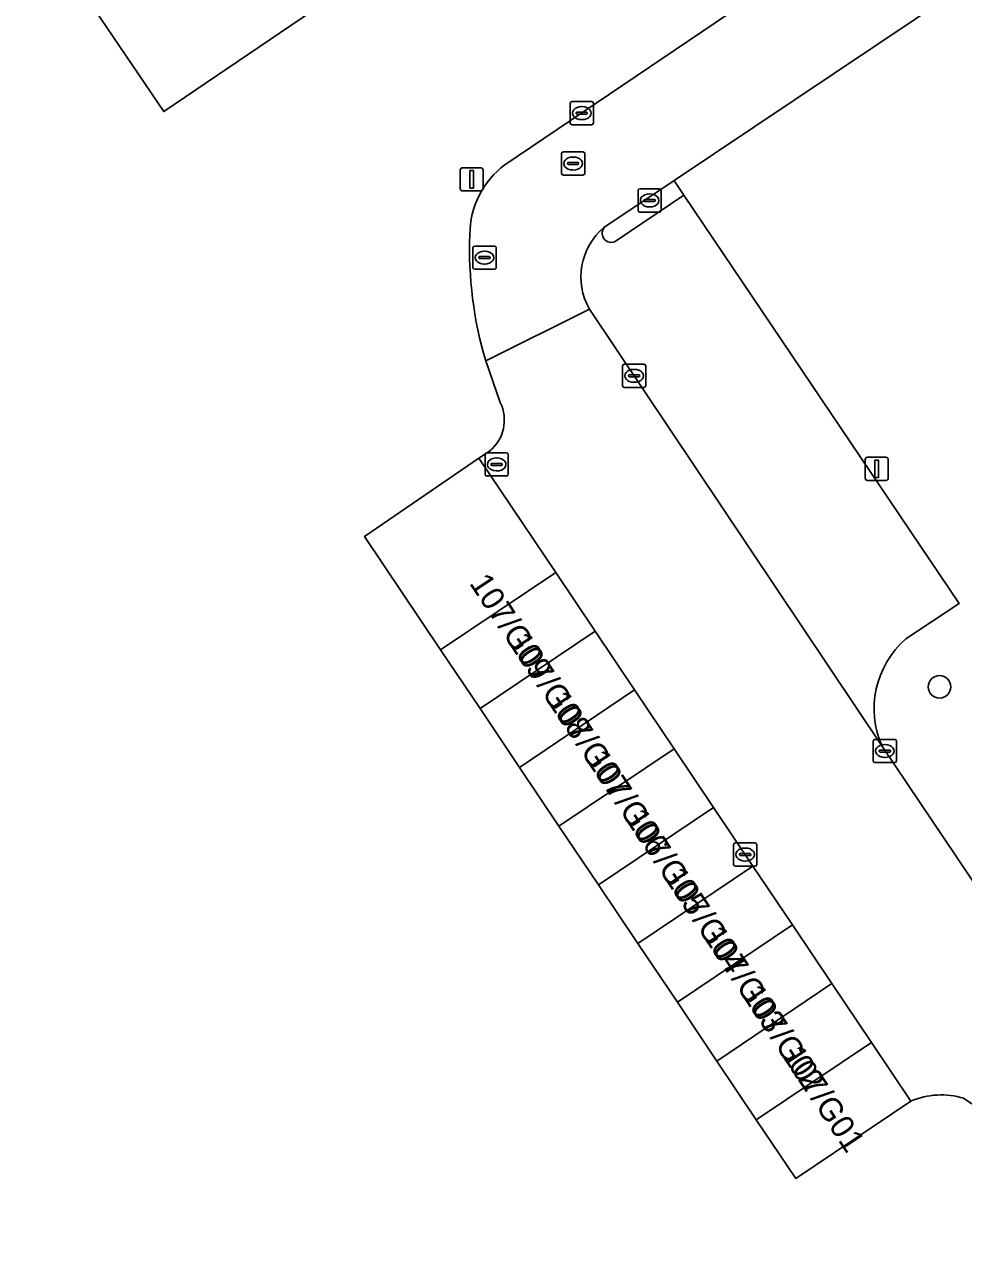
# Model space of a CAD drawing. Extents: x 157445 to 158888, y 383061 to 384688.
# Drawn here: x 157824.2 to 157864.7, y 383505.8 to 383558.3 of the extents above; entities that cross this region are included whole.
import ezdxf

# ---------------------------------------------------------------- set-up
doc = ezdxf.new("R2010")
doc.units = 0
for name, color, linetype in [('IMGEO_Boom', 7, 'Continuous'), ('IMGEO_Brandkraan', 7, 'Continuous'), ('IMGEO_Erf', 7, 'Continuous'), ('IMGEO_Kolk', 7, 'Continuous'), ('IMGEO_Lichtmast', 7, 'Continuous'), ('IMGEO_Pand', 7, 'Continuous'), ('IMGEO_Pand_nummerreeks', 7, 'Continuous'), ('IMGEO_Parkeervlak_open', 7, 'Continuous'), ('IMGEO_Rijbaan_lokaal_open', 7, 'Continuous'), ('IMGEO_Rioolput', 7, 'Continuous'), ('IMGEO_Voetpad_open', 7, 'Continuous')]:
    doc.layers.add(name, color=color, linetype=linetype)

msp = doc.modelspace()

# ---------------------------------------------------------------- linework, layer by layer
at = {"layer": 'IMGEO_Boom'}
msp.add_circle((157863.674, 383529.745), 0.489, dxfattribs=at)
at = {"layer": 'IMGEO_Brandkraan'}
for p, q in [((157847.376, 383551.876), (157847.376, 383552.728)), ((157847.451, 383552.802), (157848.303, 383552.802)), ((157848.377, 383552.728), (157848.377, 383551.876)), ((157847.635, 383552.296), (157847.635, 383552.308)), ((157848.073, 383552.259), (157847.675, 383552.259)), ((157847.678, 383552.345), (157848.076, 383552.345)), ((157847.864, 383552.582), (157847.889, 383552.582)), ((157848.119, 383552.308), (157848.119, 383552.296)), ((157848.303, 383551.802), (157847.451, 383551.802)), ((157847.887, 383552.022), (157847.862, 383552.022))]:
    msp.add_line(p, q, dxfattribs=at)
for points in [[(157847.376, 383551.876), (157847.376, 383552.728)], [(157847.451, 383552.802), (157848.303, 383552.802)], [(157848.377, 383552.728), (157848.377, 383551.876)], [(157848.303, 383551.802), (157847.451, 383551.802)]]:
    msp.add_lwpolyline(points, dxfattribs=at)
for centre, radius, start, end in [((157847.453, 383552.726), 0.0765, 91.552, 178.448), ((157847.453, 383552.726), 0.0765, 91.552, 178.448), ((157848.301, 383552.726), 0.0765, 1.552, 88.448), ((157848.301, 383552.726), 0.0765, 1.552, 88.448), ((157847.675, 383552.305), 0.0403, 85.8775, 175.7526), ((157847.672, 383552.295), 0.0366, 178.938, 274.7102), ((157848.076, 383552.302), 0.043, 264.8664, 352.4533), ((157848.08, 383552.307), 0.0386, 1.7309, 96.639), ((157847.453, 383551.878), 0.0765, 181.552, 268.448), ((157847.453, 383551.878), 0.0765, 181.552, 268.448), ((157848.301, 383551.878), 0.0765, 271.552, 358.448), ((157848.301, 383551.878), 0.0765, 271.552, 358.448)]:
    msp.add_arc(centre, radius, start, end, dxfattribs=at)
for centre, major_axis, ratio, start_param, end_param in [((157847.863, 383552.302), (-0.387, 0.002), 0.722429, 4.712389, 7.853982), ((157847.888, 383552.302), (-0.39, 0.002), 0.717154, 1.570796, 4.712389)]:
    msp.add_ellipse(centre, major_axis=major_axis, ratio=ratio, start_param=start_param, end_param=end_param, dxfattribs=at)
at = {"layer": 'IMGEO_Erf'}
msp.add_lwpolyline([(157844.882, 383564.471), (157830.231, 383554.54), (157824.218, 383563.411), (157838.87, 383573.342), (157853.625, 383583.343), (157868.277, 383593.274), (157874.289, 383584.403), (157859.638, 383574.472)], close=True, dxfattribs=at)
for points in [[(157844.94, 383552.247), (157889.043, 383582.032), (157889.621, 383582.56), (157887.417, 383584.862), (157886.541, 383585.652), (157884.838, 383587.206), (157882.528, 383589.266)], [(157905.879, 383567.073), (157893.465, 383579.161), (157891.88, 383578.119), (157852.229, 383551.572), (157852.305, 383551.459), (157852.656, 383550.938), (157864.518, 383533.336), (157862.221, 383531.81)], [(157844.739, 383541.998), (157844.108, 383543.792)], [(157862.438, 383511.892), (157857.477, 383508.557), (157855.776, 383511.088), (157854.074, 383513.62), (157852.373, 383516.151), (157850.672, 383518.683), (157848.97, 383521.214), (157847.269, 383523.746), (157845.568, 383526.277), (157843.866, 383528.809), (157842.165, 383531.34), (157838.89, 383536.227), (157843.816, 383539.6), (157844.269, 383539.91)], [(157861.211, 383527.166), (157873.422, 383509.028)], [(157869.642, 383505.834), (157866.134, 383511.051), (157864.716, 383512.012)]]:
    msp.add_lwpolyline(points, dxfattribs=at)
for centre, radius, start, end in [((157847.183, 383549.232), 3.758, 126.642, 179.8012), ((157860.364, 383548.597), 16.951, 177.8104, 196.4681), ((157843.203, 383541.247), 1.71, 308.5698, 26.059), ((157864.833, 383528.81), 3.977, 131.0422, 204.418), ((157863.743, 383508.809), 3.348, 73.0947, 112.9362)]:
    msp.add_arc(centre, radius, start, end, dxfattribs=at)
at = {"layer": 'IMGEO_Kolk'}
for p, q in [((157847.752, 383554.047), (157847.752, 383554.899)), ((157847.827, 383554.973), (157848.679, 383554.973)), ((157848.753, 383554.899), (157848.753, 383554.047)), ((157848.011, 383554.467), (157848.011, 383554.479)), ((157848.449, 383554.43), (157848.051, 383554.43)), ((157848.054, 383554.516), (157848.452, 383554.516)), ((157848.24, 383554.753), (157848.265, 383554.753)), ((157848.495, 383554.479), (157848.495, 383554.467)), ((157848.679, 383553.973), (157847.827, 383553.973)), ((157848.263, 383554.193), (157848.238, 383554.193)), ((157850.677, 383550.285), (157850.677, 383551.137)), ((157850.752, 383551.211), (157851.604, 383551.211)), ((157851.678, 383551.137), (157851.678, 383550.285)), ((157850.936, 383550.705), (157850.936, 383550.717)), ((157851.374, 383550.668), (157850.976, 383550.668)), ((157850.979, 383550.754), (157851.377, 383550.754)), ((157851.165, 383550.991), (157851.19, 383550.991)), ((157851.42, 383550.717), (157851.42, 383550.705)), ((157851.604, 383550.211), (157850.752, 383550.211)), ((157851.188, 383550.431), (157851.163, 383550.431)), ((157850.007, 383542.725), (157850.007, 383543.577)), ((157850.082, 383543.651), (157850.934, 383543.651)), ((157850.495, 383543.431), (157850.52, 383543.431)), ((157851.008, 383543.577), (157851.008, 383542.725)), ((157850.266, 383543.145), (157850.266, 383543.157)), ((157850.704, 383543.108), (157850.306, 383543.108)), ((157850.309, 383543.194), (157850.707, 383543.194)), ((157850.518, 383542.871), (157850.493, 383542.871)), ((157850.75, 383543.157), (157850.75, 383543.145)), ((157850.934, 383542.651), (157850.082, 383542.651)), ((157844.081, 383538.908), (157844.081, 383539.76)), ((157844.156, 383539.834), (157845.008, 383539.834)), ((157844.569, 383539.614), (157844.594, 383539.614)), ((157845.082, 383539.76), (157845.082, 383538.908)), ((157844.34, 383539.328), (157844.34, 383539.34)), ((157844.778, 383539.291), (157844.38, 383539.291)), ((157844.383, 383539.377), (157844.781, 383539.377)), ((157844.592, 383539.054), (157844.567, 383539.054)), ((157844.824, 383539.34), (157844.824, 383539.328)), ((157845.008, 383538.834), (157844.156, 383538.834)), ((157860.818, 383526.554), (157860.818, 383527.406)), ((157860.893, 383527.48), (157861.745, 383527.48)), ((157861.077, 383526.974), (157861.077, 383526.986)), ((157861.12, 383527.023), (157861.518, 383527.023)), ((157861.306, 383527.26), (157861.331, 383527.26)), ((157861.561, 383526.986), (157861.561, 383526.974)), ((157861.819, 383527.406), (157861.819, 383526.554)), ((157861.745, 383526.48), (157860.893, 383526.48)), ((157861.515, 383526.937), (157861.117, 383526.937)), ((157861.329, 383526.7), (157861.304, 383526.7)), ((157854.798, 383522.091), (157854.798, 383522.943)), ((157854.873, 383523.017), (157855.725, 383523.017)), ((157855.286, 383522.797), (157855.311, 383522.797)), ((157855.799, 383522.943), (157855.799, 383522.091)), ((157855.057, 383522.511), (157855.057, 383522.523)), ((157855.495, 383522.474), (157855.097, 383522.474)), ((157855.1, 383522.56), (157855.498, 383522.56)), ((157855.541, 383522.523), (157855.541, 383522.511)), ((157855.725, 383522.017), (157854.873, 383522.017)), ((157855.309, 383522.237), (157855.284, 383522.237))]:
    msp.add_line(p, q, dxfattribs=at)
for points in [[(157847.752, 383554.047), (157847.752, 383554.899)], [(157847.827, 383554.973), (157848.679, 383554.973)], [(157848.753, 383554.899), (157848.753, 383554.047)], [(157848.679, 383553.973), (157847.827, 383553.973)], [(157850.677, 383550.285), (157850.677, 383551.137)], [(157850.752, 383551.211), (157851.604, 383551.211)], [(157851.678, 383551.137), (157851.678, 383550.285)], [(157851.604, 383550.211), (157850.752, 383550.211)], [(157850.007, 383542.725), (157850.007, 383543.577)], [(157850.082, 383543.651), (157850.934, 383543.651)], [(157851.008, 383543.577), (157851.008, 383542.725)], [(157850.934, 383542.651), (157850.082, 383542.651)], [(157844.081, 383538.908), (157844.081, 383539.76)], [(157844.156, 383539.834), (157845.008, 383539.834)], [(157845.082, 383539.76), (157845.082, 383538.908)], [(157845.008, 383538.834), (157844.156, 383538.834)], [(157860.818, 383526.554), (157860.818, 383527.406)], [(157860.893, 383527.48), (157861.745, 383527.48)], [(157861.819, 383527.406), (157861.819, 383526.554)], [(157861.745, 383526.48), (157860.893, 383526.48)], [(157854.798, 383522.091), (157854.798, 383522.943)], [(157854.873, 383523.017), (157855.725, 383523.017)], [(157855.799, 383522.943), (157855.799, 383522.091)], [(157855.725, 383522.017), (157854.873, 383522.017)]]:
    msp.add_lwpolyline(points, dxfattribs=at)
for centre, radius, start, end in [((157847.829, 383554.897), 0.0765, 91.552, 178.448), ((157847.829, 383554.897), 0.0765, 91.552, 178.448), ((157848.677, 383554.897), 0.0765, 1.552, 88.448), ((157848.677, 383554.897), 0.0765, 1.552, 88.448), ((157848.051, 383554.476), 0.0403, 85.8775, 175.7526), ((157848.048, 383554.466), 0.0366, 178.938, 274.7102), ((157848.452, 383554.473), 0.043, 264.8664, 352.4533), ((157848.456, 383554.478), 0.0386, 1.7309, 96.639), ((157847.829, 383554.049), 0.0765, 181.552, 268.448), ((157847.829, 383554.049), 0.0765, 181.552, 268.448), ((157848.677, 383554.049), 0.0765, 271.552, 358.448), ((157848.677, 383554.049), 0.0765, 271.552, 358.448), ((157850.754, 383551.135), 0.0765, 91.552, 178.448), ((157850.754, 383551.135), 0.0765, 91.552, 178.448), ((157851.602, 383551.135), 0.0765, 1.552, 88.448), ((157851.602, 383551.135), 0.0765, 1.552, 88.448), ((157850.976, 383550.714), 0.0403, 85.8775, 175.7526), ((157850.973, 383550.704), 0.0366, 178.938, 274.7102), ((157851.377, 383550.711), 0.043, 264.8664, 352.4533), ((157851.381, 383550.716), 0.0386, 1.7309, 96.639), ((157850.754, 383550.287), 0.0765, 181.552, 268.448), ((157850.754, 383550.287), 0.0765, 181.552, 268.448), ((157851.602, 383550.287), 0.0765, 271.552, 358.448), ((157851.602, 383550.287), 0.0765, 271.552, 358.448), ((157850.084, 383543.575), 0.0765, 91.552, 178.448), ((157850.084, 383543.575), 0.0765, 91.552, 178.448), ((157850.932, 383543.575), 0.0765, 1.552, 88.448), ((157850.932, 383543.575), 0.0765, 1.552, 88.448), ((157850.084, 383542.727), 0.0765, 181.552, 268.448), ((157850.084, 383542.727), 0.0765, 181.552, 268.448), ((157850.306, 383543.154), 0.0403, 85.8775, 175.7526), ((157850.303, 383543.144), 0.0366, 178.938, 274.7102), ((157850.707, 383543.151), 0.043, 264.8664, 352.4533), ((157850.711, 383543.156), 0.0386, 1.7309, 96.639), ((157850.932, 383542.727), 0.0765, 271.552, 358.448), ((157850.932, 383542.727), 0.0765, 271.552, 358.448), ((157844.158, 383539.758), 0.0765, 91.552, 178.448), ((157844.158, 383539.758), 0.0765, 91.552, 178.448), ((157845.006, 383539.758), 0.0765, 1.552, 88.448), ((157845.006, 383539.758), 0.0765, 1.552, 88.448), ((157844.38, 383539.337), 0.0403, 85.8775, 175.7526), ((157844.377, 383539.327), 0.0366, 178.938, 274.7102), ((157844.781, 383539.334), 0.043, 264.8664, 352.4533), ((157844.785, 383539.339), 0.0386, 1.7309, 96.639), ((157844.158, 383538.91), 0.0765, 181.552, 268.448), ((157844.158, 383538.91), 0.0765, 181.552, 268.448), ((157845.006, 383538.91), 0.0765, 271.552, 358.448), ((157845.006, 383538.91), 0.0765, 271.552, 358.448), ((157860.895, 383527.404), 0.0765, 91.552, 178.448), ((157860.895, 383527.404), 0.0765, 91.552, 178.448), ((157861.117, 383526.983), 0.0403, 85.8775, 175.7526), ((157861.522, 383526.985), 0.0386, 1.7309, 96.639), ((157861.743, 383527.404), 0.0765, 1.552, 88.448), ((157861.743, 383527.404), 0.0765, 1.552, 88.448), ((157860.895, 383526.556), 0.0765, 181.552, 268.448), ((157860.895, 383526.556), 0.0765, 181.552, 268.448), ((157861.114, 383526.973), 0.0366, 178.938, 274.7102), ((157861.518, 383526.98), 0.043, 264.8664, 352.4533), ((157861.743, 383526.556), 0.0765, 271.552, 358.448), ((157861.743, 383526.556), 0.0765, 271.552, 358.448), ((157854.875, 383522.941), 0.0765, 91.552, 178.448), ((157854.875, 383522.941), 0.0765, 91.552, 178.448), ((157855.723, 383522.941), 0.0765, 1.552, 88.448), ((157855.723, 383522.941), 0.0765, 1.552, 88.448), ((157855.097, 383522.52), 0.0403, 85.8775, 175.7526), ((157855.094, 383522.51), 0.0366, 178.938, 274.7102), ((157855.498, 383522.517), 0.043, 264.8664, 352.4533), ((157855.502, 383522.522), 0.0386, 1.7309, 96.639), ((157854.875, 383522.093), 0.0765, 181.552, 268.448), ((157854.875, 383522.093), 0.0765, 181.552, 268.448), ((157855.723, 383522.093), 0.0765, 271.552, 358.448), ((157855.723, 383522.093), 0.0765, 271.552, 358.448)]:
    msp.add_arc(centre, radius, start, end, dxfattribs=at)
for centre, major_axis, ratio, start_param, end_param in [((157848.239, 383554.473), (-0.387, 0.002), 0.722429, 4.712389, 7.853982), ((157848.264, 383554.473), (-0.39, 0.002), 0.717154, 1.570796, 4.712389), ((157851.164, 383550.711), (-0.387, 0.002), 0.722429, 4.712389, 7.853982), ((157851.189, 383550.711), (-0.39, 0.002), 0.717154, 1.570796, 4.712389), ((157850.494, 383543.151), (-0.387, 0.002), 0.722429, 4.712389, 7.853982), ((157850.519, 383543.151), (-0.39, 0.002), 0.717154, 1.570796, 4.712389), ((157844.568, 383539.334), (-0.387, 0.002), 0.722429, 4.712389, 7.853982), ((157844.593, 383539.334), (-0.39, 0.002), 0.717154, 1.570796, 4.712389), ((157861.305, 383526.98), (-0.387, 0.002), 0.722429, 4.712389, 7.853982), ((157861.33, 383526.98), (-0.39, 0.002), 0.717154, 1.570796, 4.712389), ((157855.285, 383522.517), (-0.387, 0.002), 0.722429, 4.712389, 7.853982), ((157855.31, 383522.517), (-0.39, 0.002), 0.717154, 1.570796, 4.712389)]:
    msp.add_ellipse(centre, major_axis=major_axis, ratio=ratio, start_param=start_param, end_param=end_param, dxfattribs=at)
at = {"layer": 'IMGEO_Lichtmast'}
for p, q in [((157843.01, 383551.22), (157843.01, 383552.02)), ((157843.01, 383552.02), (157843.01, 383551.22)), ((157843.11, 383552.12), (157843.9, 383552.12)), ((157843.9, 383552.12), (157843.11, 383552.12)), ((157844, 383552.02), (157844, 383551.22)), ((157844, 383551.22), (157844, 383552.02)), ((157843.9, 383551.12), (157843.11, 383551.12)), ((157843.11, 383551.12), (157843.9, 383551.12)), ((157860.572, 383539.644), (157861.362, 383539.644)), ((157861.362, 383539.644), (157860.572, 383539.644)), ((157860.472, 383538.744), (157860.472, 383539.544)), ((157860.472, 383539.544), (157860.472, 383538.744)), ((157861.462, 383539.544), (157861.462, 383538.744)), ((157861.462, 383538.744), (157861.462, 383539.544)), ((157861.362, 383538.644), (157860.572, 383538.644)), ((157860.572, 383538.644), (157861.362, 383538.644))]:
    msp.add_line(p, q, dxfattribs=at)
for points in [[(157843.43, 383551.995), (157843.58, 383551.995), (157843.58, 383551.245), (157843.43, 383551.245), (157843.43, 383551.995)], [(157860.892, 383539.519), (157861.042, 383539.519), (157861.042, 383538.769), (157860.892, 383538.769), (157860.892, 383539.519)]]:
    msp.add_lwpolyline(points, dxfattribs=at)
for centre, start, end in [((157843.11, 383552.02), 90, 180), ((157843.11, 383552.02), 90, 180), ((157843.9, 383552.02), 0, 90), ((157843.9, 383552.02), 360, 90), ((157843.11, 383551.22), 180, 270), ((157843.11, 383551.22), 180, 270), ((157843.9, 383551.22), 270, 0), ((157843.9, 383551.22), 270, 0), ((157860.572, 383539.544), 90, 180), ((157860.572, 383539.544), 90, 180), ((157861.362, 383539.544), 0, 90), ((157861.362, 383539.544), 360, 90), ((157860.572, 383538.744), 180, 270), ((157860.572, 383538.744), 180, 270), ((157861.362, 383538.744), 270, 0), ((157861.362, 383538.744), 270, 0)]:
    msp.add_arc(centre, 0.1, start, end, dxfattribs=at)
at = {"layer": 'IMGEO_Pand'}
for points in [[(157838.87, 383573.342), (157824.218, 383563.411), (157830.231, 383554.54), (157844.882, 383564.471)], [(157848.827, 383532.143), (157847.126, 383534.674), (157842.165, 383531.34), (157843.866, 383528.809)], [(157848.827, 383532.143), (157843.866, 383528.809), (157845.568, 383526.277), (157850.529, 383529.611)], [(157845.568, 383526.277), (157847.269, 383523.746), (157852.23, 383527.08), (157850.529, 383529.611)], [(157848.97, 383521.214), (157853.931, 383524.548), (157852.23, 383527.08), (157847.269, 383523.746)], [(157855.633, 383522.017), (157853.931, 383524.548), (157848.97, 383521.214), (157850.672, 383518.683)], [(157855.633, 383522.017), (157850.672, 383518.683), (157852.373, 383516.151), (157857.334, 383519.486)], [(157859.036, 383516.954), (157857.334, 383519.486), (157852.373, 383516.151), (157854.074, 383513.62)], [(157859.036, 383516.954), (157854.074, 383513.62), (157855.776, 383511.088), (157860.737, 383514.423)], [(157860.737, 383514.423), (157855.776, 383511.088), (157857.477, 383508.557), (157862.438, 383511.892)]]:
    msp.add_lwpolyline(points, close=True, dxfattribs=at)
at = {"layer": 'IMGEO_Parkeervlak_open'}
for points in [[(157852.656, 383550.938), (157849.734, 383548.968)], [(157862.221, 383531.81), (157864.518, 383533.336), (157852.656, 383550.938)], [(157849.294, 383549.607), (157849.204, 383549.545)], [(157848.58, 383546.028), (157861.211, 383527.166)]]:
    msp.add_lwpolyline(points, dxfattribs=at)
for centre, radius, start, end in [((157849.518, 383549.29), 0.388, 125.1965, 303.9043), ((157851.011, 383547.411), 2.796, 130.2483, 209.6298), ((157864.833, 383528.81), 3.977, 131.0422, 204.418)]:
    msp.add_arc(centre, radius, start, end, dxfattribs=at)
at = {"layer": 'IMGEO_Rijbaan_lokaal_open'}
for points in [[(157891.88, 383578.119), (157889.043, 383582.032), (157844.94, 383552.247)], [(157849.204, 383549.545), (157849.294, 383549.607), (157852.229, 383551.572), (157891.88, 383578.119)], [(157873.422, 383509.028), (157861.211, 383527.166), (157848.58, 383546.028), (157844.108, 383543.792), (157844.739, 383541.998)], [(157844.108, 383543.792), (157848.58, 383546.028)], [(157844.269, 383539.91), (157843.816, 383539.6), (157847.126, 383534.674), (157848.827, 383532.143), (157850.529, 383529.611), (157852.23, 383527.08), (157853.931, 383524.548), (157855.633, 383522.017), (157857.334, 383519.486), (157859.036, 383516.954), (157860.737, 383514.423), (157862.438, 383511.892)], [(157864.716, 383512.012), (157866.134, 383511.051), (157869.642, 383505.834)]]:
    msp.add_lwpolyline(points, dxfattribs=at)
msp.add_lwpolyline([(157843.816, 383539.6), (157838.89, 383536.227), (157842.165, 383531.34), (157847.126, 383534.674)], close=True, dxfattribs=at)
for centre, radius, start, end in [((157847.183, 383549.232), 3.758, 126.642, 179.8012), ((157860.364, 383548.597), 16.951, 177.8104, 196.4681), ((157851.011, 383547.411), 2.796, 130.2483, 209.6298), ((157843.203, 383541.247), 1.71, 308.5698, 26.059), ((157863.743, 383508.809), 3.348, 73.0947, 112.9362)]:
    msp.add_arc(centre, radius, start, end, dxfattribs=at)
at = {"layer": 'IMGEO_Rioolput'}
for p, q in [((157843.56, 383547.818), (157843.56, 383548.67)), ((157843.635, 383548.744), (157844.487, 383548.744)), ((157844.048, 383548.524), (157844.073, 383548.524)), ((157844.561, 383548.67), (157844.561, 383547.818)), ((157843.819, 383548.238), (157843.819, 383548.25)), ((157844.257, 383548.201), (157843.859, 383548.201)), ((157843.862, 383548.287), (157844.26, 383548.287)), ((157844.303, 383548.25), (157844.303, 383548.238)), ((157844.487, 383547.744), (157843.635, 383547.744)), ((157844.071, 383547.964), (157844.046, 383547.964))]:
    msp.add_line(p, q, dxfattribs=at)
for points in [[(157843.56, 383547.818), (157843.56, 383548.67)], [(157843.635, 383548.744), (157844.487, 383548.744)], [(157844.561, 383548.67), (157844.561, 383547.818)], [(157844.487, 383547.744), (157843.635, 383547.744)]]:
    msp.add_lwpolyline(points, dxfattribs=at)
for centre, radius, start, end in [((157843.637, 383548.668), 0.0765, 91.552, 178.448), ((157843.637, 383548.668), 0.0765, 91.552, 178.448), ((157844.485, 383548.668), 0.0765, 1.552, 88.448), ((157844.485, 383548.668), 0.0765, 1.552, 88.448), ((157843.859, 383548.247), 0.0403, 85.8775, 175.7526), ((157843.856, 383548.237), 0.0366, 178.938, 274.7102), ((157844.26, 383548.244), 0.043, 264.8664, 352.4533), ((157844.264, 383548.249), 0.0386, 1.7309, 96.639), ((157843.637, 383547.82), 0.0765, 181.552, 268.448), ((157843.637, 383547.82), 0.0765, 181.552, 268.448), ((157844.485, 383547.82), 0.0765, 271.552, 358.448), ((157844.485, 383547.82), 0.0765, 271.552, 358.448)]:
    msp.add_arc(centre, radius, start, end, dxfattribs=at)
for centre, major_axis, ratio, start_param, end_param in [((157844.047, 383548.244), (-0.387, 0.002), 0.722429, 4.712389, 7.853982), ((157844.072, 383548.244), (-0.39, 0.002), 0.717154, 1.570796, 4.712389)]:
    msp.add_ellipse(centre, major_axis=major_axis, ratio=ratio, start_param=start_param, end_param=end_param, dxfattribs=at)
at = {"layer": 'IMGEO_Voetpad_open'}
for points in [[(157852.656, 383550.938), (157852.305, 383551.459), (157852.229, 383551.572), (157849.294, 383549.607)], [(157849.734, 383548.968), (157852.656, 383550.938)]]:
    msp.add_lwpolyline(points, dxfattribs=at)
msp.add_arc((157849.518, 383549.29), 0.388, 125.1965, 303.9043, dxfattribs=at)

# ---------------------------------------------------------------- texts
at = {"layer": 'IMGEO_Pand_nummerreeks'}
for s, p in [('107/G09', (157843.377, 383534.212)), ('107/G08', (157845.057, 383531.675)), ('107/G07', (157846.732, 383529.147)), ('107/G06', (157848.41, 383526.615)), ('107/G05', (157850.087, 383524.084)), ('107/G04', (157851.764, 383521.553)), ('107/G03', (157853.441, 383519.022)), ('107/G02', (157855.114, 383516.496)), ('107/G01', (157856.856, 383513.867))]:
    msp.add_text(s, height=1, rotation=303.5265, dxfattribs=at).set_placement(p)

doc.saveas('drawing.dxf')
